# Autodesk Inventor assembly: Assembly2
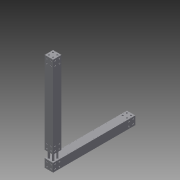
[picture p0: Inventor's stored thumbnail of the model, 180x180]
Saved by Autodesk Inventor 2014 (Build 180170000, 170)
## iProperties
Created: 2014-06
Part Number: Assembly2
Document SubType Name: Assembly
Designer: Aser
Author: Aser
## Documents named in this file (3)
- C:\Users\Aser\Documents\Assembly2.iam
- C:\Users\Aser\Documents\Assembly1.iam
- C:\Users\Aser\Documents\Spoke.iam
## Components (6 placed, 2 different names)
1. Assembly1:1 [sub-assembly] — Mate:1, Mate:2, Mate:3, Mate:4, Mate:5, Mate:6, Mate:7, Mate:8, Mate:9, Mate:10, Mate:11, Mate:12, Flush:4, Flush:5
2. Assembly1:2 [sub-assembly] — Flush:4, Flush:5
3. Spoke:1 [sub-assembly] — Flush:3, Mate:10, Mate:11, Mate:12
4. Spoke:2 [sub-assembly] — Flush:2, Mate:8, Mate:9
5. Spoke:3 [sub-assembly] — Mate:1, Mate:2, Mate:3, Mate:4, Mate:5, Flush:1, Flush:2, Flush:3
6. Spoke:4 [sub-assembly] — Flush:1, Mate:6, Mate:7
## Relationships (17: Mate 12, Flush 5)
- Mate:1: Assembly1:1 ↔ Spoke:3
- Mate:2: Assembly1:1 ↔ Spoke:3
- Mate:3: Assembly1:1 ↔ Spoke:3
- Mate:4: Assembly1:1 ↔ Spoke:3
- Mate:5: Assembly1:1 ↔ Spoke:3
- Flush:1: Spoke:3 ↔ Spoke:4
- Flush:2: Spoke:2 ↔ Spoke:3
- Flush:3: Spoke:1 ↔ Spoke:3
- Mate:6: Assembly1:1 ↔ Spoke:4
- Mate:7: Assembly1:1 ↔ Spoke:4
- Mate:8: Assembly1:1 ↔ Spoke:2
- Mate:9: Assembly1:1 ↔ Spoke:2
- Mate:10: Assembly1:1 ↔ Spoke:1
- Mate:11: Assembly1:1 ↔ Spoke:1
- Mate:12: Assembly1:1 ↔ Spoke:1
- Flush:4: Assembly1:1 ↔ Assembly1:2
- Flush:5: Assembly1:1 ↔ Assembly1:2
